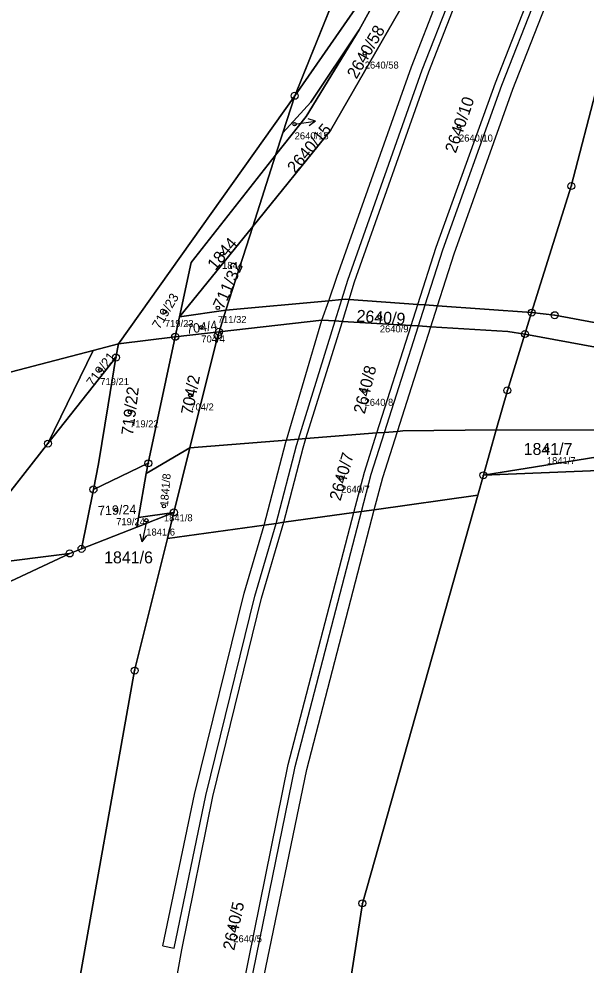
# Model space of a CAD drawing. Extents: x -653098 to -649479, y -997642 to -992666.
# Drawn here: x -652256.7 to -652175.9, y -994728.1 to -994593.4 of the extents above; entities that cross this region are included whole.
import ezdxf

# ---------------------------------------------------------------- set-up
doc = ezdxf.new("R2010")
doc.units = 0
for name, color, linetype in [('Definiční body', 7, 'Continuous'), ('Hranice parcel', 7, 'Continuous'), ('Parcelní čísla', 7, 'Continuous'), ('Polygon parcely', 7, 'Continuous'), ('Pop  PČ popisy', 7, 'Continuous'), ('Vnitřní kresba', 7, 'Continuous'), ('Značky bodu BP', 7, 'Continuous')]:
    doc.layers.add(name, color=color, linetype=linetype)

msp = doc.modelspace()

# ---------------------------------------------------------------- linework, layer by layer
at = {"layer": 'Definiční body'}
for centre in [(-652207.41, -994598.27), (-652217.4, -994608.35), (-652193.99, -994608.67), (-652227.74, -994626.81), (-652228.35, -994634.51), (-652235.89, -994635.08), (-652205.27, -994635.85), (-652230.7, -994637.28), (-652245.1, -994643.36), (-652207.44, -994646.31), (-652232.27, -994646.97), (-652240.87, -994649.38), (-652181.46, -994654.62), (-652210.78, -994658.7), (-652236.03, -994662.76), (-652242.83, -994663.31), (-652238.54, -994664.79), (-652226.15, -994722.72)]:
    msp.add_circle(centre, 0.25, dxfattribs=at)
at = {"layer": 'Hranice parcel'}
for p, q in [((-652217.39, -994604.31), (-652207.77, -994580.54)), ((-652200.95, -994580.63), (-652217.39, -994604.31)), ((-652208.21, -994594.93), (-652200.91, -994581.66)), ((-652242.49, -994639.64), (-652217.39, -994604.31)), ((-652217.39, -994604.31), (-652219.08, -994609.57)), ((-652220.11, -994612.77), (-652219.08, -994609.57)), ((-652223.36, -994622.91), (-652220.11, -994612.77)), ((-652223.36, -994622.91), (-652233.82, -994635.81)), ((-652227.2, -994634.86), (-652223.36, -994622.91)), ((-652233.82, -994635.81), (-652227.2, -994634.86)), ((-652227.2, -994634.86), (-652228.18, -994637.93)), ((-652184.58, -994638.25), (-652183.63, -994635.19)), ((-652234.42, -994638.64), (-652233.82, -994635.81)), ((-652228.18, -994637.93), (-652234.42, -994638.64)), ((-652246.12, -994640.59), (-652242.49, -994639.64)), ((-652242.87, -994641.59), (-652242.49, -994639.64)), ((-652234.42, -994638.64), (-652242.49, -994639.64)), ((-652238.26, -994656.66), (-652234.42, -994638.64)), ((-652252.55, -994653.85), (-652246.12, -994640.59)), ((-652252.55, -994653.85), (-652242.87, -994641.59)), ((-652188.68, -994651.9), (-652201.99, -994652.05)), ((-652190.51, -994658.36), (-652188.68, -994651.9)), ((-652188.68, -994651.9), (-652140.11, -994652.01)), ((-652201.99, -994652.05), (-652202.76, -994652.11)), ((-652238.57, -994658.11), (-652232.32, -994654.44)), ((-652232.32, -994654.44), (-652234.61, -994663.66)), ((-652246.07, -994660.39), (-652238.26, -994656.66)), ((-652238.26, -994656.66), (-652238.57, -994658.11)), ((-652238.57, -994658.11), (-652239.66, -994664.37)), ((-652190.51, -994658.36), (-652191.32, -994661.21)), ((-652247.77, -994668.84), (-652246.07, -994660.39)), ((-652234.61, -994663.66), (-652239.9, -994665.74)), ((-652234.61, -994663.66), (-652239.66, -994664.37)), ((-652235.53, -994667.38), (-652234.61, -994663.66)), ((-652239.66, -994664.37), (-652239.9, -994665.74)), ((-652239.9, -994665.74), (-652247.77, -994668.84)), ((-652247.77, -994668.84), (-652249.45, -994669.5))]:
    msp.add_line(p, q, dxfattribs=at)
for points in [[(-652196.88, -994582.45), (-652212.27, -994609.23), (-652223.36, -994622.91)], [(-652170.51, -994588.25), (-652177.99, -994617.17), (-652183.63, -994635.19)], [(-652220.11, -994612.77), (-652215.74, -994607.24), (-652208.21, -994594.93)], [(-652208.21, -994594.93), (-652215.1, -994605.21), (-652219.08, -994609.57)], [(-652233.82, -994635.81), (-652232.17, -994628.04), (-652220.11, -994612.77)], [(-652183.63, -994635.19), (-652197.06, -994634.22), (-652198.81, -994634.1), (-652199.85, -994634.02), (-652209.63, -994633.32), (-652210.12, -994633.28), (-652210.66, -994633.33), (-652212.54, -994633.5), (-652227.2, -994634.86)], [(-652183.63, -994635.19), (-652180.34, -994635.56), (-652157.15, -994639.88), (-652135.52, -994652.11)], [(-652184.58, -994638.25), (-652187.01, -994637.86), (-652198.01, -994637.2), (-652199.76, -994637.09), (-652200.81, -994637.03), (-652210.6, -994636.44), (-652211.61, -994636.37), (-652213.51, -994636.26), (-652228.18, -994637.93)], [(-652228.18, -994637.93), (-652228.35, -994638.45), (-652232.32, -994654.44)], [(-652188.68, -994651.9), (-652187.09, -994646.27), (-652184.58, -994638.25)], [(-652140.11, -994652.01), (-652157.49, -994643.27), (-652184.58, -994638.25)], [(-652608.95, -994697.69), (-652536.02, -994673.36), (-652510.59, -994668.89), (-652402.69, -994666.21), (-652363.9, -994660.26), (-652326.36, -994661.26), (-652326.75, -994658.15), (-652286.74, -994651.16), (-652246.12, -994640.59)], [(-652242.87, -994641.59), (-652243.96, -994648.32), (-652245.33, -994656.73), (-652246.07, -994660.39)], [(-652202.76, -994652.11), (-652204.6, -994652.26), (-652205.69, -994652.34), (-652215.8, -994653.14), (-652216.87, -994653.22), (-652218.56, -994653.36), (-652232.32, -994654.44)], [(-652190.51, -994658.36), (-652168.27, -994654.8), (-652140.11, -994652.01)], [(-652582.58, -994793.28), (-652564.33, -994786.91), (-652550.56, -994782.1), (-652521.84, -994771.16), (-652497.37, -994765.74), (-652454.73, -994761.65), (-652389.49, -994727.36), (-652356.91, -994706.57), (-652310.85, -994690.47), (-652271.12, -994672.09), (-652268.36, -994671.05), (-652260.26, -994663.62), (-652252.55, -994653.85)], [(-651862.11, -994711.75), (-651891.78, -994706.62), (-651996.79, -994680.38), (-652060.95, -994669.31), (-652095.93, -994663.72), (-652120.99, -994656.99), (-652143.52, -994656.46), (-652190.51, -994658.36)], [(-652191.32, -994661.21), (-652206.05, -994663.27), (-652207.88, -994663.52), (-652208.96, -994663.67), (-652218.94, -994665.06), (-652220.02, -994665.22), (-652221.74, -994665.46), (-652235.53, -994667.38)], [(-652191.32, -994661.21), (-652207.75, -994719.34), (-652225.62, -994834.33)], [(-652255.61, -994850.31), (-652256.68, -994823.75), (-652254.71, -994780.26), (-652253.2, -994768.62), (-652248.81, -994734.49), (-652240.2, -994686.19), (-652235.53, -994667.38)], [(-652453, -994767.66), (-652432.87, -994758.78), (-652386.5, -994732.06), (-652354.92, -994711.91), (-652309.09, -994694.8), (-652268.5, -994676.87), (-652261.2, -994670.96), (-652249.45, -994669.5)], [(-652249.45, -994669.5), (-652301.83, -994694.07), (-652353.63, -994713.75), (-652370.4, -994723.15)]]:
    msp.add_lwpolyline(points, dxfattribs=at)
at = {"layer": 'Polygon parcely'}
for points in [[(-652217.39, -994604.31), (-652219.08, -994609.57), (-652215.1, -994605.21), (-652208.21, -994594.93), (-652200.91, -994581.66), (-652200.03, -994580.07), (-652183.05, -994547.7), (-652169.31, -994508.1), (-652170.45, -994507.86), (-652187.08, -994551.75), (-652200.95, -994580.63)], [(-652536.02, -994673.36), (-652510.59, -994668.89), (-652402.69, -994666.21), (-652363.9, -994660.26), (-652326.36, -994661.26), (-652326.75, -994658.15), (-652286.74, -994651.16), (-652246.12, -994640.59), (-652242.49, -994639.64), (-652217.39, -994604.31), (-652207.77, -994580.54), (-652218.48, -994580.4), (-652227.41, -994580.28), (-652229.21, -994580.26), (-652269.05, -994581.78), (-652397.88, -994601.18), (-652554.26, -994620.63), (-652595.99, -994631.33), (-652643.95, -994645.12), (-652648.09, -994646.67), (-652613.28, -994690.97), (-652608.95, -994697.69)], [(-652207.77, -994580.54), (-652217.39, -994604.31), (-652200.95, -994580.63)], [(-652220.11, -994612.77), (-652223.36, -994622.91), (-652212.27, -994609.23), (-652196.88, -994582.45), (-652200.91, -994581.66), (-652208.21, -994594.93), (-652215.74, -994607.24)], [(-652191.49, -994583.5), (-652192.46, -994583.31), (-652194.08, -994583), (-652196.88, -994582.45), (-652212.27, -994609.23), (-652223.36, -994622.91), (-652227.2, -994634.86), (-652212.54, -994633.5), (-652210.66, -994633.33), (-652210.12, -994633.28), (-652209.63, -994633.32), (-652199.85, -994634.02), (-652198.81, -994634.1), (-652197.06, -994634.22), (-652183.63, -994635.19), (-652177.99, -994617.17), (-652170.51, -994588.25), (-652179.53, -994586.08), (-652181.17, -994585.69), (-652182.16, -994585.45), (-652184.9, -994584.79)], [(-652180.34, -994635.56), (-652157.15, -994639.88), (-652135.52, -994652.11), (-652121.26, -994652.45), (-651984.82, -994678.96), (-651920.56, -994694.6), (-651916.7, -994695.46), (-651916.45, -994651.43), (-651934.09, -994648.23), (-651961.12, -994643.19), (-651993.42, -994637.17), (-652017.83, -994633.26), (-652042.57, -994629.37), (-652067.09, -994623.25), (-652096.14, -994616.18), (-652127.91, -994608.85), (-652157.35, -994602.1), (-652156.9, -994600.15), (-652154.86, -994592.01), (-652170.51, -994588.25), (-652177.99, -994617.17), (-652183.63, -994635.19)], [(-652219.08, -994609.57), (-652220.11, -994612.77), (-652215.74, -994607.24), (-652208.21, -994594.93), (-652215.1, -994605.21)], [(-652220.11, -994612.77), (-652219.08, -994609.57), (-652217.39, -994604.31), (-652242.49, -994639.64), (-652234.42, -994638.64), (-652233.82, -994635.81), (-652232.17, -994628.04)], [(-652233.82, -994635.81), (-652223.36, -994622.91), (-652220.11, -994612.77), (-652232.17, -994628.04)], [(-652227.2, -994634.86), (-652223.36, -994622.91), (-652233.82, -994635.81)], [(-652227.2, -994634.86), (-652228.18, -994637.93), (-652213.51, -994636.26), (-652211.61, -994636.37), (-652210.6, -994636.44), (-652200.81, -994637.03), (-652199.76, -994637.09), (-652198.01, -994637.2), (-652187.01, -994637.86), (-652184.58, -994638.25), (-652183.63, -994635.19), (-652197.06, -994634.22), (-652198.81, -994634.1), (-652199.85, -994634.02), (-652209.63, -994633.32), (-652210.12, -994633.28), (-652210.66, -994633.33), (-652212.54, -994633.5)], [(-652233.82, -994635.81), (-652234.42, -994638.64), (-652228.18, -994637.93), (-652227.2, -994634.86)], [(-652135.52, -994652.11), (-652157.15, -994639.88), (-652180.34, -994635.56), (-652183.63, -994635.19), (-652184.58, -994638.25), (-652157.49, -994643.27), (-652140.11, -994652.01)], [(-652228.35, -994638.45), (-652232.32, -994654.44), (-652218.56, -994653.36), (-652216.87, -994653.22), (-652215.8, -994653.14), (-652205.69, -994652.34), (-652204.6, -994652.26), (-652202.76, -994652.11), (-652201.99, -994652.05), (-652188.68, -994651.9), (-652187.09, -994646.27), (-652184.58, -994638.25), (-652187.01, -994637.86), (-652198.01, -994637.2), (-652199.76, -994637.09), (-652200.81, -994637.03), (-652210.6, -994636.44), (-652211.61, -994636.37), (-652213.51, -994636.26), (-652228.18, -994637.93)], [(-652234.42, -994638.64), (-652238.26, -994656.66), (-652238.57, -994658.11), (-652232.32, -994654.44), (-652228.35, -994638.45), (-652228.18, -994637.93)], [(-652140.11, -994652.01), (-652157.49, -994643.27), (-652184.58, -994638.25), (-652187.09, -994646.27), (-652188.68, -994651.9)], [(-652242.87, -994641.59), (-652242.49, -994639.64), (-652246.12, -994640.59), (-652252.55, -994653.85)], [(-652242.49, -994639.64), (-652242.87, -994641.59), (-652243.96, -994648.32), (-652245.33, -994656.73), (-652246.07, -994660.39), (-652238.26, -994656.66), (-652234.42, -994638.64)], [(-652201.99, -994652.05), (-652202.76, -994652.11), (-652204.6, -994652.26), (-652205.69, -994652.34), (-652215.8, -994653.14), (-652216.87, -994653.22), (-652218.56, -994653.36), (-652232.32, -994654.44), (-652234.61, -994663.66), (-652235.53, -994667.38), (-652221.74, -994665.46), (-652220.02, -994665.22), (-652218.94, -994665.06), (-652208.96, -994663.67), (-652207.88, -994663.52), (-652206.05, -994663.27), (-652191.32, -994661.21), (-652190.51, -994658.36), (-652188.68, -994651.9)], [(-652168.27, -994654.8), (-652140.11, -994652.01), (-652188.68, -994651.9), (-652190.51, -994658.36)], [(-652238.57, -994658.11), (-652239.66, -994664.37), (-652234.61, -994663.66), (-652232.32, -994654.44)], [(-652238.26, -994656.66), (-652246.07, -994660.39), (-652247.77, -994668.84), (-652239.9, -994665.74), (-652239.66, -994664.37), (-652238.57, -994658.11)], [(-651862.11, -994711.75), (-651891.78, -994706.62), (-651996.79, -994680.38), (-652060.95, -994669.31), (-652095.93, -994663.72), (-652120.99, -994656.99), (-652143.52, -994656.46), (-652190.51, -994658.36), (-652191.32, -994661.21), (-652207.75, -994719.34), (-652225.62, -994834.33), (-652192.88, -994836.21), (-652193.33, -994837.97), (-652192.32, -994840.96), (-652176.18, -994835.19), (-652167.83, -994833.96), (-652134.26, -994829.85), (-652109.71, -994831.46), (-652137, -994752.18), (-652068.56, -994769.31), (-651985.26, -994782.48), (-651897.58, -994793.47), (-651870.23, -994798.31)], [(-652218.94, -994665.06), (-652220.02, -994665.22), (-652221.74, -994665.46), (-652235.53, -994667.38), (-652240.2, -994686.19), (-652248.81, -994734.49), (-652253.2, -994768.62), (-652254.71, -994780.26), (-652256.68, -994823.75), (-652255.61, -994850.31), (-652246.8, -994849.01), (-652227.07, -994846.09), (-652226.79, -994843.79), (-652225.62, -994834.33), (-652207.75, -994719.34), (-652191.32, -994661.21), (-652206.05, -994663.27), (-652207.88, -994663.52), (-652208.96, -994663.67)], [(-652360.45, -994732.18), (-652353.17, -994772.6), (-652412.56, -994772.27), (-652389.02, -994830.52), (-652381.92, -994832.42), (-652342.05, -994844.52), (-652319.31, -994847.46), (-652293.55, -994850.5), (-652255.61, -994850.31), (-652256.68, -994823.75), (-652254.71, -994780.26), (-652253.2, -994768.62), (-652248.81, -994734.49), (-652240.2, -994686.19), (-652235.53, -994667.38), (-652234.61, -994663.66), (-652239.9, -994665.74), (-652247.77, -994668.84), (-652249.45, -994669.5), (-652301.83, -994694.07), (-652353.63, -994713.75), (-652370.4, -994723.15)], [(-652239.66, -994664.37), (-652239.9, -994665.74), (-652234.61, -994663.66)], [(-652370.4, -994723.15), (-652353.63, -994713.75), (-652301.83, -994694.07), (-652249.45, -994669.5), (-652261.2, -994670.96), (-652268.5, -994676.87), (-652309.09, -994694.8), (-652354.92, -994711.91), (-652386.5, -994732.06), (-652432.87, -994758.78), (-652453, -994767.66), (-652440.84, -994764.71), (-652399.69, -994743.59), (-652376.5, -994727.33)]]:
    msp.add_lwpolyline(points, close=True, dxfattribs=at)
for points in [[(-652497.37, -994765.74), (-652454.73, -994761.65), (-652389.49, -994727.36), (-652356.91, -994706.57), (-652310.85, -994690.47), (-652271.12, -994672.09), (-652268.36, -994671.05), (-652260.26, -994663.62), (-652252.55, -994653.85), (-652246.12, -994640.59), (-652286.74, -994651.16), (-652326.75, -994658.15), (-652326.36, -994661.26), (-652363.9, -994660.26), (-652402.69, -994666.21), (-652510.59, -994668.89)], [(-652489.88, -994773.96), (-652468.47, -994771.8), (-652453, -994767.66), (-652432.87, -994758.78), (-652386.5, -994732.06), (-652354.92, -994711.91), (-652309.09, -994694.8), (-652268.5, -994676.87), (-652261.2, -994670.96), (-652249.45, -994669.5), (-652247.77, -994668.84), (-652246.07, -994660.39), (-652245.33, -994656.73), (-652243.96, -994648.32), (-652242.87, -994641.59), (-652252.55, -994653.85), (-652260.26, -994663.62), (-652268.36, -994671.05), (-652271.12, -994672.09), (-652310.85, -994690.47), (-652356.91, -994706.57), (-652389.49, -994727.36), (-652454.73, -994761.65), (-652497.37, -994765.74)], [(-651837.94, -994708.26), (-651869.76, -994703.31), (-651886.32, -994701.83), (-651890.65, -994701.44), (-651899.7, -994699.88), (-651914.72, -994695.97), (-651916.7, -994695.46), (-651920.56, -994694.6), (-651984.82, -994678.96), (-652121.26, -994652.45), (-652135.52, -994652.11), (-652140.11, -994652.01), (-652168.27, -994654.8), (-652190.51, -994658.36), (-652143.52, -994656.46), (-652120.99, -994656.99), (-652095.93, -994663.72), (-652060.95, -994669.31), (-651996.79, -994680.38), (-651891.78, -994706.62), (-651862.11, -994711.75), (-651822.91, -994719.34)]]:
    msp.add_lwpolyline(points, dxfattribs=at)
at = {"layer": 'Pop  PČ popisy'}
for p, q in [((-652217.4, -994608.35), (-652214.43, -994607.93)), ((-652214.43, -994607.93), (-652215.49, -994607.58)), ((-652214.43, -994607.93), (-652215.35, -994608.57)), ((-652238.52, -994664.89), (-652239.14, -994667.83)), ((-652239.14, -994667.83), (-652239.43, -994666.74)), ((-652239.14, -994667.83), (-652238.45, -994666.95))]:
    msp.add_line(p, q, dxfattribs=at)
at = {"layer": 'Vnitřní kresba'}
for p, q in [((-652200.76, -994600.2), (-652194.08, -994583)), ((-652199.22, -994600.63), (-652192.46, -994583.31)), ((-652198.28, -994600.9), (-652191.49, -994583.5)), ((-652188.8, -994602.47), (-652182.16, -994585.45)), ((-652187.88, -994602.8), (-652181.17, -994585.69)), ((-652186.33, -994603.36), (-652179.53, -994586.08)), ((-652211.37, -994630.16), (-652200.76, -994600.2)), ((-652209.8, -994630.57), (-652199.22, -994600.63)), ((-652208.85, -994630.82), (-652198.28, -994600.9)), ((-652197.26, -994625.89), (-652188.8, -994602.47)), ((-652196.3, -994626.23), (-652187.88, -994602.8)), ((-652194.69, -994626.8), (-652186.33, -994603.36)), ((-652199.85, -994634.02), (-652197.26, -994625.89)), ((-652198.81, -994634.1), (-652196.3, -994626.23)), ((-652197.06, -994634.22), (-652194.69, -994626.8)), ((-652212.54, -994633.5), (-652211.37, -994630.16)), ((-652210.66, -994633.33), (-652209.8, -994630.57)), ((-652209.63, -994633.32), (-652208.85, -994630.82)), ((-652213.51, -994636.26), (-652212.54, -994633.5)), ((-652211.61, -994636.37), (-652210.66, -994633.33)), ((-652210.6, -994636.44), (-652209.63, -994633.32)), ((-652200.81, -994637.03), (-652199.85, -994634.02)), ((-652199.76, -994637.09), (-652198.81, -994634.1)), ((-652198.01, -994637.2), (-652197.06, -994634.22)), ((-652218.56, -994653.36), (-652213.51, -994636.26)), ((-652216.87, -994653.22), (-652211.61, -994636.37)), ((-652215.8, -994653.14), (-652210.6, -994636.44)), ((-652205.69, -994652.34), (-652200.81, -994637.03)), ((-652204.6, -994652.26), (-652199.76, -994637.09)), ((-652202.76, -994652.11), (-652198.01, -994637.2)), ((-652217.16, -994654.14), (-652216.87, -994653.22)), ((-652216.21, -994654.45), (-652215.8, -994653.14)), ((-652207.46, -994657.91), (-652205.69, -994652.34)), ((-652206.5, -994658.2), (-652204.6, -994652.26)), ((-652204.86, -994658.68), (-652202.76, -994652.11)), ((-652221.74, -994665.46), (-652218.65, -994653.65)), ((-652220.02, -994665.22), (-652217.16, -994654.14)), ((-652218.94, -994665.06), (-652216.21, -994654.45)), ((-652218.65, -994653.65), (-652218.56, -994653.36)), ((-652208.96, -994663.67), (-652207.46, -994657.91)), ((-652207.88, -994663.52), (-652206.5, -994658.2)), ((-652206.05, -994663.27), (-652204.86, -994658.68)), ((-652218.31, -994699.58), (-652208.96, -994663.67)), ((-652217.33, -994699.84), (-652207.88, -994663.52)), ((-652215.68, -994700.28), (-652206.05, -994663.27)), ((-652223.08, -994675.59), (-652220.02, -994665.22)), ((-652222.12, -994675.88), (-652218.94, -994665.06)), ((-652224.58, -994675.14), (-652221.74, -994665.46)), ((-652231.68, -994703.82), (-652224.58, -994675.14)), ((-652230.08, -994704), (-652223.08, -994675.59)), ((-652229.07, -994704.11), (-652222.12, -994675.88)), ((-652226.01, -994737.37), (-652218.31, -994699.58)), ((-652225.04, -994737.47), (-652217.33, -994699.84)), ((-652223.4, -994737.64), (-652215.68, -994700.28)), ((-652236.18, -994725.39), (-652231.68, -994703.82)), ((-652234.56, -994725.71), (-652230.08, -994704)), ((-652233.48, -994725.94), (-652229.07, -994704.11)), ((-652236.72, -994743.84), (-652233.48, -994725.94)), ((-652236.18, -994725.39), (-652234.56, -994725.71))]:
    msp.add_line(p, q, dxfattribs=at)
at = {"layer": 'Značky bodu BP'}
for centre, radius in [((-652217.39, -994604.31), 0.5), ((-652217.39, -994604.31), 0.0303), ((-652177.99, -994617.17), 0.5), ((-652177.99, -994617.17), 0.0303), ((-652183.63, -994635.19), 0.5), ((-652183.63, -994635.19), 0.0303), ((-652180.34, -994635.56), 0.5), ((-652180.34, -994635.56), 0.0303), ((-652234.42, -994638.64), 0.5), ((-652228.35, -994638.45), 0.5), ((-652228.18, -994637.93), 0.5), ((-652228.35, -994638.45), 0.0303), ((-652228.18, -994637.93), 0.0303), ((-652184.58, -994638.25), 0.5), ((-652184.58, -994638.25), 0.0303), ((-652234.42, -994638.64), 0.0303), ((-652242.87, -994641.59), 0.5), ((-652242.87, -994641.59), 0.0303), ((-652187.09, -994646.27), 0.5), ((-652187.09, -994646.27), 0.0303), ((-652252.55, -994653.85), 0.5), ((-652252.55, -994653.85), 0.0303), ((-652238.26, -994656.66), 0.5), ((-652238.26, -994656.66), 0.0303), ((-652190.51, -994658.36), 0.5), ((-652190.51, -994658.36), 0.0303), ((-652246.07, -994660.39), 0.5), ((-652246.07, -994660.39), 0.0303), ((-652234.61, -994663.66), 0.5), ((-652234.61, -994663.66), 0.0303), ((-652249.45, -994669.5), 0.5), ((-652249.45, -994669.5), 0.0303), ((-652247.77, -994668.84), 0.5), ((-652247.77, -994668.84), 0.0303), ((-652240.2, -994686.19), 0.5), ((-652240.2, -994686.19), 0.0303), ((-652207.75, -994719.34), 0.5), ((-652207.75, -994719.34), 0.0303)]:
    msp.add_circle(centre, radius, dxfattribs=at)

# ---------------------------------------------------------------- texts
at = {"layer": 'Definiční body'}
for s, p in [('2640/58', (-652207.41, -994600.43)), ('2640/15', (-652217.4, -994610.51)), ('2640/10', (-652193.99, -994610.83)), ('1844', (-652227.74, -994628.97)), ('711/32', (-652228.35, -994636.67)), ('719/23', (-652235.89, -994637.24)), ('2640/9', (-652205.27, -994638.01)), ('704/4', (-652230.7, -994639.44)), ('719/21', (-652245.1, -994645.52)), ('2640/8', (-652207.44, -994648.47)), ('704/2', (-652232.27, -994649.13)), ('719/22', (-652240.87, -994651.54)), ('1841/7', (-652181.46, -994656.78)), ('2640/7', (-652210.78, -994660.86)), ('1841/8', (-652236.03, -994664.92)), ('719/24', (-652242.83, -994665.47)), ('1841/6', (-652238.54, -994666.95)), ('2640/5', (-652226.15, -994724.88))]:
    msp.add_text(s, height=1, dxfattribs=at).set_placement(p)
at = {"layer": 'Parcelní čísla'}
for s, height, rotation, p in [('2640/58', 1.7, 60, (-652208.59, -994602.02)), ('2640/10', 1.7, 71, (-652194.44, -994612.58)), ('2640/15', 1.7, 50, (-652217.33, -994615.47)), ('1844', 1.7, 50, (-652228.7, -994629.28)), ('711/32', 1.7, 66, (-652227.57, -994634.85)), ('719/23', 1.337, 59, (-652236.66, -994637.65)), ('2640/9', 1.7, 356, (-652208.63, -994636.47)), ('704/4', 1.337, 8, (-652232.77, -994638.24)), ('719/21', 1.337, 53, (-652246.13, -994645.84)), ('2640/8', 1.7, 76, (-652207.41, -994649.72)), ('704/2', 1.7, 79, (-652231.96, -994649.85)), ('719/22', 1.7, 83, (-652240.43, -994652.76)), ('2640/7', 1.7, 74, (-652210.87, -994662.11)), ('1841/8', 1.14, 85, (-652235.46, -994662.81)), ('719/24', 1.337, 2, (-652245.4, -994664.07)), ('2640/5', 1.7, 78, (-652226.01, -994726.13))]:
    msp.add_text(s, height=height, rotation=rotation, dxfattribs=at).set_placement(p)
for s, p in [('1841/7', (-652184.77, -994655.47)), ('1841/6', (-652244.55, -994670.91))]:
    msp.add_text(s, height=1.7, dxfattribs=at).set_placement(p)

doc.saveas('drawing.dxf')
